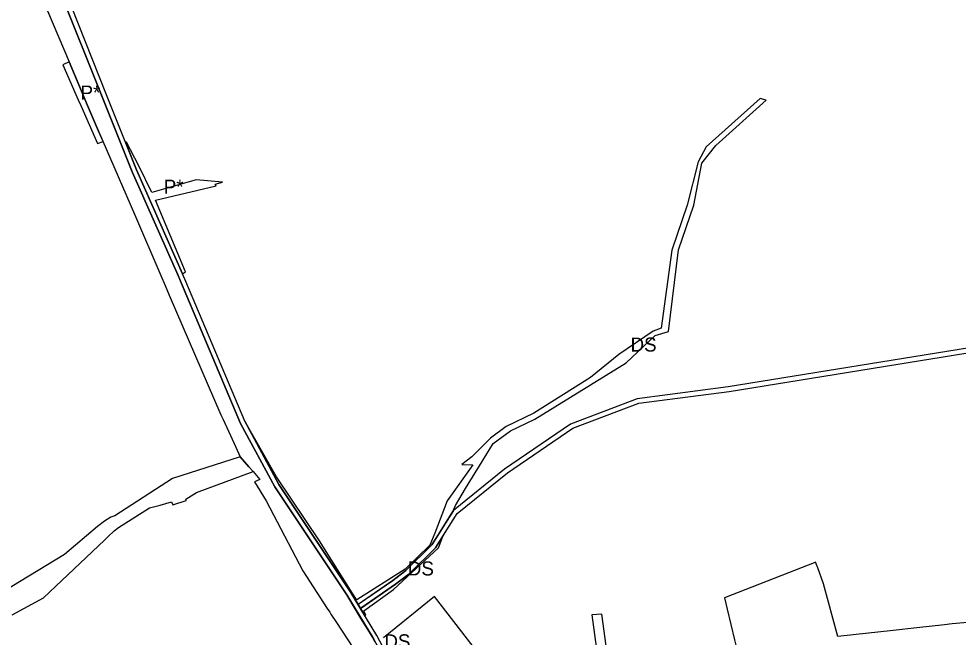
# Model space of a CAD drawing. Extents: x -477304 to -465641, y -1159113 to -1149285.
# Drawn here: x -475290 to -474688, y -1154138 to -1153742 of the extents above; entities that cross this region are included whole.
import ezdxf

# ---------------------------------------------------------------- set-up
doc = ezdxf.new("R2010")
doc.units = 0
for name, color, linetype in [('14', 7, 'Continuous'), ('34', 7, 'Continuous'), ('35', 7, 'Continuous')]:
    doc.layers.add(name, color=color, linetype=linetype)

msp = doc.modelspace()

# ---------------------------------------------------------------- linework, layer by layer
at = {"layer": '14'}
for p, q in [((-474673.04, -1153951.25), (-474834.98, -1153977.52)), ((-474834.5, -1153980.48), (-474674.9, -1153954.6)), ((-474834.98, -1153977.52), (-474893.44, -1153985.04)), ((-474892.37, -1153987.84), (-474834.5, -1153980.48)), ((-475072.32, -1154116.86), (-475070.76, -1154119.43))]:
    msp.add_line(p, q, dxfattribs=at)
for points in [[(-475263.98, -1153722.73), (-475236.41, -1153791.63), (-475217.01, -1153839.71), (-475187.63, -1153906.18), (-475185.4, -1153911.23), (-475147.69, -1154000.85), (-475125.66, -1154041.48), (-475079.55, -1154110.73), (-475062.93, -1154138.13), (-475053.54, -1154155.81)], [(-475070.54, -1154119.8), (-475077.01, -1154109.12), (-475123.09, -1154039.93), (-475144.98, -1153999.55), (-475182.65, -1153910.04), (-475184.89, -1153904.97), (-475214.25, -1153838.54), (-475233.62, -1153790.51), (-475256.01, -1153733.93)], [(-474893.44, -1153985.04), (-474936.06, -1154001.33), (-474978.37, -1154030.22), (-475011.03, -1154056.62), (-475025, -1154078.67), (-475041.72, -1154095.19), (-475050.04, -1154101.53), (-475072.32, -1154116.86)], [(-475070.76, -1154119.43), (-475048.28, -1154103.96), (-475039.75, -1154097.46), (-475022.65, -1154080.56), (-475008.76, -1154058.65), (-474976.58, -1154032.63), (-474934.66, -1154004), (-474892.37, -1153987.84)], [(-475050.89, -1154154.4), (-475060.32, -1154136.65), (-475070.54, -1154119.8)]]:
    msp.add_lwpolyline(points, dxfattribs=at)
at = {"layer": '34'}
for p, q in [((-475257.5, -1153769.35), (-475261.64, -1153771.18)), ((-475261.64, -1153771.18), (-475251.68, -1153793.63)), ((-475247.81, -1153792.17), (-475257.5, -1153769.35)), ((-475251.68, -1153793.63), (-475250.03, -1153797.34)), ((-475246.27, -1153795.8), (-475247.81, -1153792.17)), ((-475238.66, -1153813.69), (-475246.27, -1153795.8)), ((-475250.03, -1153797.34), (-475239.24, -1153821.65)), ((-475235.76, -1153820.38), (-475238.66, -1153813.69)), ((-475239.24, -1153821.65), (-475235.76, -1153820.38)), ((-475220.72, -1153820.65), (-475221.42, -1153820.76)), ((-475221.42, -1153820.76), (-475214.25, -1153838.54)), ((-475212.93, -1153835.96), (-475220.72, -1153820.65)), ((-475204.41, -1153852.95), (-475212.93, -1153835.96)), ((-475176.04, -1153844.83), (-475204.41, -1153852.95)), ((-475159.2, -1153846.3), (-475176.04, -1153844.83)), ((-475163.9, -1153847.56), (-475159.2, -1153846.3)), ((-475163.36, -1153848.67), (-475163.9, -1153847.56)), ((-475182.95, -1153903.76), (-475192.84, -1153880.33)), ((-475175.9, -1154045.24), (-475139.56, -1154031.8)), ((-475139.56, -1154031.8), (-475142.35, -1154028.6)), ((-475225.81, -1154067.63), (-475206.02, -1154054.87)), ((-475206.02, -1154054.87), (-475199.18, -1154053.17)), ((-475199.18, -1154053.17), (-475191.83, -1154051.03)), ((-475191.83, -1154051.03), (-475191.13, -1154053.11)), ((-475230.76, -1154061.05), (-475234.9, -1154063.53)), ((-475228.21, -1154060.16), (-475230.76, -1154061.05)), ((-475239.39, -1154066.92), (-475260.41, -1154084.94)), ((-475234.9, -1154063.53), (-475239.39, -1154066.92)), ((-475228.59, -1154069.67), (-475225.81, -1154067.63)), ((-475234.87, -1154075.63), (-475232.75, -1154073.61)), ((-475232.75, -1154073.61), (-475228.59, -1154069.67)), ((-475262.28, -1154101.62), (-475234.87, -1154075.63)), ((-475273.91, -1154112.63), (-475262.28, -1154101.62)), ((-475293.92, -1154123.61), (-475273.91, -1154112.63)), ((-475023.31, -1154111.7), (-475056.07, -1154138.22)), ((-474998.43, -1154143.87), (-475023.31, -1154111.7)), ((-474916.14, -1154123.06), (-474922.51, -1154123.49)), ((-474922.51, -1154123.49), (-474918.97, -1154148.69)), ((-474912.63, -1154148.06), (-474916.14, -1154123.06))]:
    msp.add_line(p, q, dxfattribs=at)
for points in [[(-475214.25, -1153838.54), (-475184.89, -1153904.97), (-475182.95, -1153903.76)], [(-475192.84, -1153880.33), (-475202.25, -1153857.8), (-475163.36, -1153848.67)], [(-475142.35, -1154028.6), (-475147.88, -1154022.24), (-475191.27, -1154036.13), (-475228.21, -1154060.16)], [(-475191.13, -1154053.11), (-475182.59, -1154050.21), (-475182.62, -1154049.46), (-475175.9, -1154045.24)], [(-475260.41, -1154084.94), (-475300.17, -1154108.93), (-475319.6, -1154119.7)]]:
    msp.add_lwpolyline(points, dxfattribs=at)
at = {"layer": '35'}
for p, q in [((-475280.57, -1153715.08), (-475257.5, -1153769.35)), ((-475257.5, -1153769.35), (-475247.81, -1153792.17)), ((-475247.81, -1153792.17), (-475246.27, -1153795.8)), ((-474814.55, -1153792.85), (-474849.16, -1153823.66)), ((-474843.05, -1153822.86), (-474810.81, -1153793.9)), ((-474810.81, -1153793.9), (-474814.55, -1153792.85)), ((-474849.16, -1153823.66), (-474854.3, -1153833.39)), ((-474851.93, -1153834.19), (-474843.05, -1153822.86)), ((-474857.12, -1153861.1), (-474851.93, -1153834.19)), ((-475215.58, -1153866.95), (-475198.64, -1153906.05)), ((-475198.64, -1153906.05), (-475195.98, -1153912.48)), ((-474900.55, -1153962.14), (-474881.89, -1153944.67)), ((-474881.89, -1153944.67), (-474873.34, -1153941.92)), ((-475158.76, -1153998.29), (-475150.6, -1154016.17)), ((-474977.4, -1154002.81), (-474987.43, -1154010.29)), ((-474987.43, -1154010.29), (-474999.38, -1154022.22)), ((-475150.6, -1154016.17), (-475147.88, -1154022.24)), ((-475147.88, -1154022.24), (-475142.35, -1154028.6)), ((-474999.38, -1154022.22), (-475005.7, -1154027.24)), ((-475142.35, -1154028.6), (-475139.56, -1154031.8)), ((-475139.56, -1154031.8), (-475135.24, -1154036.76)), ((-474998.83, -1154027.33), (-475015.12, -1154050.38)), ((-475005.7, -1154027.24), (-474998.83, -1154027.33)), ((-475009.93, -1154053.44), (-475003.5, -1154042.64)), ((-475131.15, -1154050.49), (-475107.74, -1154095.33)), ((-475015.12, -1154050.38), (-475023.1, -1154071.3)), ((-475011.51, -1154057.39), (-475009.93, -1154053.44)), ((-475022.34, -1154074.47), (-475011.51, -1154057.39)), ((-475023.1, -1154071.3), (-475026.36, -1154078.87)), ((-475017.65, -1154072.68), (-475021.36, -1154078.53)), ((-475020.85, -1154080.64), (-475017.65, -1154072.68)), ((-475026.36, -1154078.87), (-475042.2, -1154094.29)), ((-474778.97, -1154089.81), (-474837.45, -1154112.7)), ((-474778.59, -1154090.87), (-474778.97, -1154089.81)), ((-474777.67, -1154093.44), (-474778.59, -1154090.87)), ((-475107.74, -1154095.33), (-475092.09, -1154119.38)), ((-475042.2, -1154094.29), (-475073.17, -1154113.88)), ((-474774.01, -1154103.62), (-474777.67, -1154093.44)), ((-474764.74, -1154137.45), (-474774.01, -1154103.62)), ((-475073.69, -1154113.07), (-475076.06, -1154109.37)), ((-475075.32, -1154111.91), (-475072.32, -1154116.86)), ((-475073.17, -1154113.88), (-475073.69, -1154113.07)), ((-475092.09, -1154119.38), (-475090.47, -1154121.87)), ((-475090.47, -1154121.87), (-475089.91, -1154122.72)), ((-475070.65, -1154125.4), (-475074.09, -1154119.72)), ((-475072.32, -1154116.86), (-475071.58, -1154116.35)), ((-475069.96, -1154118.88), (-475070.76, -1154119.43)), ((-475070.76, -1154119.43), (-475070.54, -1154119.8)), ((-475070.54, -1154119.8), (-475068.03, -1154123.94)), ((-475067.27, -1154123.52), (-475068.69, -1154120.85)), ((-475089.91, -1154122.72), (-475089.67, -1154123.08)), ((-475089.67, -1154123.08), (-475086.2, -1154128.4)), ((-475068.03, -1154123.94), (-475067.27, -1154123.52)), ((-475086.2, -1154128.4), (-475072, -1154149.89)), ((-474729.21, -1154133.52), (-474754.96, -1154136.37)), ((-474714.23, -1154131.89), (-474729.21, -1154133.52)), ((-474754.96, -1154136.37), (-474764.74, -1154137.45))]:
    msp.add_line(p, q, dxfattribs=at)
for points in [[(-475074.09, -1154119.72), (-475079.55, -1154110.73), (-475125.66, -1154041.48), (-475147.69, -1154000.85), (-475185.4, -1153911.23), (-475187.63, -1153906.18), (-475217.01, -1153839.71), (-475236.41, -1153791.63), (-475263.98, -1153722.73), (-475265.96, -1153718.06), (-475269.28, -1153710.13)], [(-475246.27, -1153795.8), (-475238.66, -1153813.69), (-475215.58, -1153866.95)], [(-474854.3, -1153833.39), (-474861.28, -1153861.05), (-474871.09, -1153889.86), (-474878, -1153939.78), (-474883.17, -1153941.8), (-474905.25, -1153956.69), (-474923.36, -1153971.5)], [(-474873.34, -1153941.92), (-474866.85, -1153889.7), (-474857.12, -1153861.1)], [(-475195.98, -1153912.48), (-475193.42, -1153918.67), (-475160.33, -1153995.29), (-475158.76, -1153998.29)], [(-474985.6, -1154013.82), (-474974.56, -1154005.63), (-474958.99, -1153998.09), (-474900.55, -1153962.14)], [(-474923.36, -1153971.5), (-474959.69, -1153994.34), (-474977.4, -1154002.81)], [(-475076.06, -1154109.37), (-475093.8, -1154081.17), (-475096.56, -1154076.78), (-475124.69, -1154035.14), (-475126.39, -1154032.16), (-475144.98, -1153999.55)], [(-475144.98, -1153999.55), (-475123.09, -1154039.93), (-475077.01, -1154109.12), (-475075.32, -1154111.91)], [(-475003.5, -1154042.64), (-474992.83, -1154025.38), (-474985.6, -1154013.82)], [(-475135.24, -1154036.76), (-475138.71, -1154038.27), (-475131.15, -1154050.49)], [(-475071.58, -1154116.35), (-475050.04, -1154101.53), (-475041.72, -1154095.19), (-475025, -1154078.67), (-475022.34, -1154074.47)], [(-475021.36, -1154078.53), (-475022.65, -1154080.56), (-475039.75, -1154097.46), (-475048.28, -1154103.96), (-475069.96, -1154118.88)], [(-475068.69, -1154120.85), (-475049.67, -1154107.29), (-475020.85, -1154080.64)], [(-474837.45, -1154112.7), (-474835.74, -1154119.87), (-474831.07, -1154139.46), (-474830.22, -1154143.01)], [(-475061.47, -1154140.88), (-475062.93, -1154138.13), (-475070.65, -1154125.4)], [(-474644.68, -1154125), (-474669.05, -1154127.27), (-474691.44, -1154129.37)], [(-474691.44, -1154129.37), (-474696.31, -1154129.91), (-474714.23, -1154131.89)]]:
    msp.add_lwpolyline(points, dxfattribs=at)

# ---------------------------------------------------------------- texts
at = {"layer": '34'}
for p in [(-475250.2, -1153793.44), (-475196.88, -1153853.79)]:
    msp.add_text('P*', height=9, dxfattribs=at).set_placement(p)
at = {"layer": '35'}
for p in [(-474897.65, -1153954.86), (-475040.41, -1154098.31), (-475055.45, -1154144.98)]:
    msp.add_text('DS', height=9, dxfattribs=at).set_placement(p)

doc.saveas('drawing.dxf')
